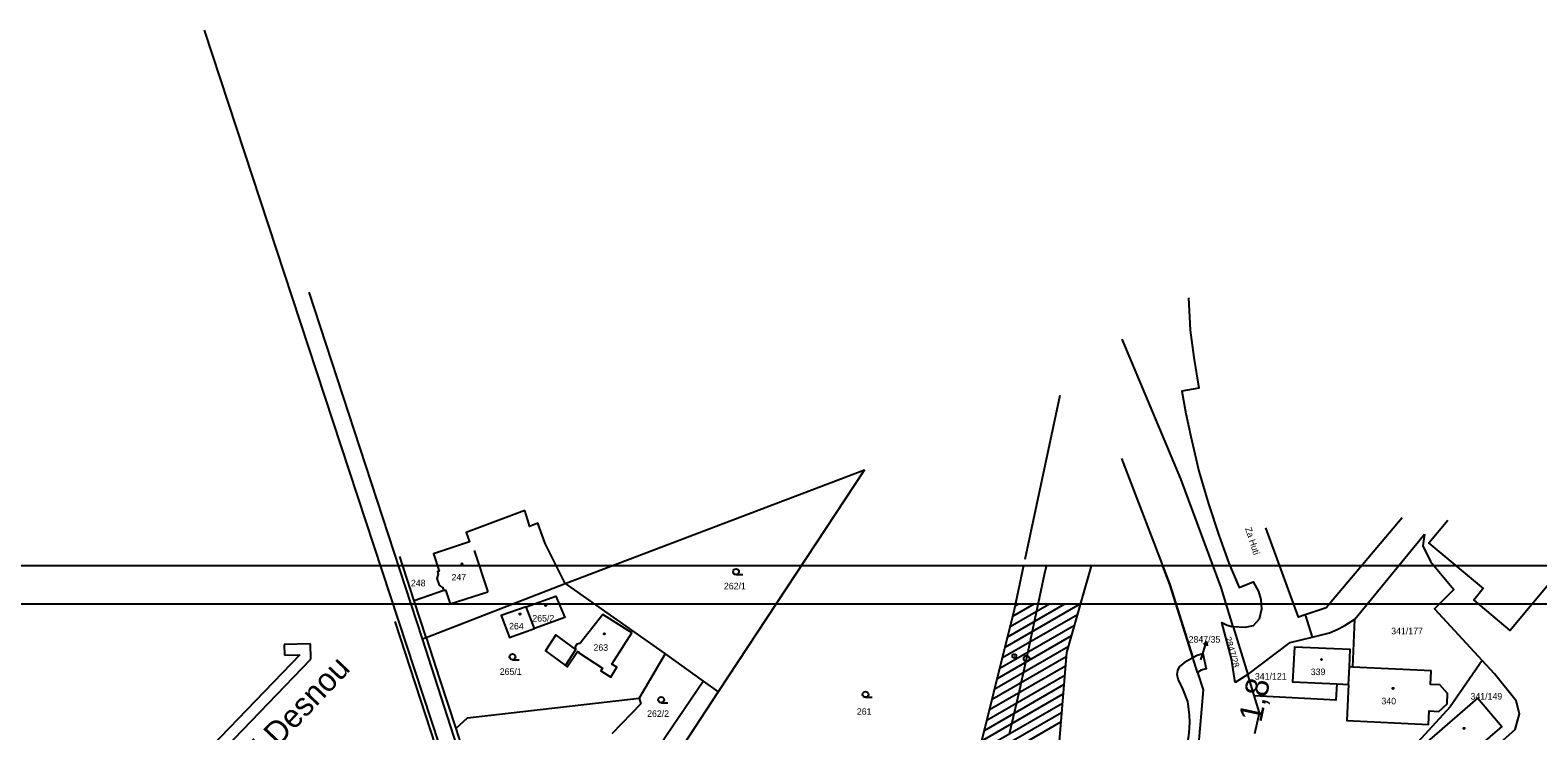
# Model space of a CAD drawing. Extents: x -558500 to -557517, y -1073973 to -1073051.
# Drawn here: x -558300.8 to -557909.9, y -1073232.9 to -1073051.2 of the extents above; entities that cross this region are included whole.
import ezdxf

# ---------------------------------------------------------------- set-up
doc = ezdxf.new("R2010")
doc.units = 0
for name, color, linetype in [('Default', 7, 'Continuous'), ('Hranice parcel', 7, 'Continuous'), ('Kolej', 7, 'Continuous'), ('Návěst místo trati', 7, 'Continuous'), ('Parcelní čísla', 7, 'Continuous'), ('Pop  PČ popisy', 7, 'Continuous'), ('Svazek obcí údolí Desné', 7, 'Continuous'), ('Vnitřní kresba', 7, 'Continuous'), ('Vrstva 1', 7, 'Continuous'), ('Značky budov', 7, 'Continuous'), ('Značky kultur', 7, 'Continuous')]:
    doc.layers.add(name, color=color, linetype=linetype)

msp = doc.modelspace()

# ---------------------------------------------------------------- linework, layer by layer
at = {"layer": 'Default'}
msp.add_lwpolyline([(-557909.21, -1073700), (-558500, -1073700), (-558500, -1073200), (-557800, -1073200), (-557800, -1073567.6)], dxfattribs=at)
at = {"layer": 'Hranice parcel'}
for p, q in [((-558199.08, -1073209.06), (-558228.45, -1073119.15)), ((-558162.11, -1073194.7), (-558084.5, -1073165.24)), ((-558084.5, -1073165.24), (-558122.4, -1073222.85)), ((-557957.38, -1073203.94), (-557939.31, -1073181.91)), ((-558201.24, -1073199.21), (-558204.98, -1073187.73)), ((-558198.15, -1073208.7), (-558162.11, -1073194.7)), ((-558162.11, -1073194.7), (-558136.18, -1073212.99)), ((-558198.15, -1073208.7), (-558201.24, -1073199.21)), ((-558170.04, -1073206.37), (-558172.21, -1073200.74)), ((-558195.64, -1073236.88), (-558206.21, -1073204.6)), ((-557990.44, -1073205.56), (-557988.88, -1073205.99)), ((-557988.88, -1073205.99), (-557985.13, -1073218.31)), ((-557985.87, -1073206.17), (-557988.88, -1073205.99)), ((-557970.23, -1073202.86), (-557968.43, -1073208.63)), ((-557957.84, -1073216.4), (-557957.38, -1073203.94)), ((-558199.08, -1073209.06), (-558198.15, -1073208.7)), ((-558171.71, -1073294.39), (-558199.08, -1073209.06)), ((-557974.16, -1073210.07), (-557968.43, -1073208.63)), ((-558136.18, -1073212.99), (-558142.95, -1073224.45)), ((-558136.18, -1073212.99), (-558126.3, -1073220.06)), ((-557999.34, -1073213.91), (-557998.27, -1073213.29)), ((-557985.13, -1073218.31), (-557974.16, -1073210.07)), ((-558000.9, -1073214.81), (-557999.34, -1073213.91)), ((-557998.11, -1073217.81), (-557999.34, -1073213.91)), ((-557997.23, -1073217.21), (-557998.11, -1073217.81)), ((-557958.95, -1073220.92), (-557958.74, -1073216.36)), ((-557957.84, -1073216.4), (-557958.74, -1073216.36)), ((-557924.3, -1073214.73), (-557932.67, -1073226.72)), ((-558140.75, -1073241.36), (-558126.3, -1073220.06)), ((-558126.3, -1073220.06), (-558122.4, -1073222.85)), ((-557985.13, -1073218.31), (-557988.34, -1073220.45)), ((-557983.46, -1073223.81), (-557985.13, -1073218.31)), ((-557961.95, -1073220.78), (-557958.95, -1073220.92)), ((-558122.4, -1073222.85), (-558147.61, -1073261.18)), ((-557932.67, -1073226.72), (-557943.85, -1073239.02)), ((-558190.48, -1073232.36), (-558186.42, -1073245.02))]:
    msp.add_line(p, q, dxfattribs=at)
for points in [[(-558194.69, -1073236.56), (-558230.74, -1073126.95), (-558255.65, -1073051.21)], [(-558000.52, -1073120.65), (-558000.04, -1073129.01), (-557999.11, -1073136.15), (-557997.8, -1073144.09), (-558002.18, -1073144.84), (-558001.16, -1073150.6), (-557999.9, -1073156.63), (-557997.77, -1073165.6), (-557995.29, -1073174.11), (-557992.59, -1073182.21), (-557990.03, -1073189.46), (-557987.35, -1073195.77), (-557983.68, -1073194.26), (-557982.33, -1073196.81), (-557981.76, -1073198.85), (-557981.57, -1073201.43), (-557982.14, -1073203.98), (-557983.75, -1073205.73), (-557985.87, -1073206.17)], [(-557988.88, -1073205.99), (-557991.98, -1073195.8), (-558002.46, -1073167.55), (-558017.66, -1073131.36)], [(-558017.89, -1073162.31), (-558005.3, -1073194.99), (-557999.34, -1073213.91)], [(-558172.6, -1073175.79), (-558187.75, -1073181.54), (-558186.95, -1073183.95), (-558196.26, -1073187), (-558194.79, -1073191.52), (-558195.22, -1073191.66), (-558195, -1073192.32), (-558195.36, -1073193.46), (-558194.8, -1073195.19), (-558193.84, -1073195.82), (-558193.6, -1073196.55), (-558201.24, -1073199.21)], [(-558162.11, -1073194.7), (-558167.28, -1073184.33), (-558169.22, -1073179.04), (-558171.35, -1073179.92), (-558171.57, -1073179.2), (-558172.6, -1073175.79)], [(-557945.06, -1073177.72), (-557964.79, -1073201.02), (-557968.13, -1073202.16), (-557970.23, -1073202.86)], [(-557933.22, -1073178.38), (-557938.16, -1073184.28), (-557924.03, -1073196.06), (-557926.52, -1073199.04), (-557917.14, -1073206.89), (-557900.5, -1073186.91)], [(-557970.23, -1073202.86), (-557971.99, -1073203.45), (-557980.44, -1073180.31)], [(-557939.31, -1073181.91), (-557939.68, -1073184.93), (-557937.77, -1073189.03), (-557931.69, -1073196.32), (-557936.68, -1073201.34), (-557924.3, -1073214.73)], [(-558172.21, -1073200.74), (-558164.51, -1073198.05), (-558162.21, -1073203.59), (-558170.04, -1073206.37)], [(-558172.21, -1073200.74), (-558178.74, -1073203.06), (-558176.58, -1073208.71), (-558170.04, -1073206.37)], [(-558159.35, -1073211.86), (-558164.49, -1073208.05), (-558167.25, -1073212.17), (-558162.05, -1073216.04), (-558161.61, -1073216.37), (-558158.87, -1073212.35), (-558158.54, -1073212.45), (-558158.65, -1073212.62), (-558152.39, -1073216.66), (-558152.86, -1073217.38), (-558150.28, -1073218.99), (-558148.7, -1073216.44), (-558149.97, -1073215.63), (-558144.81, -1073207.5), (-558152.32, -1073202.74), (-558158.11, -1073210.08), (-558158.35, -1073210.31), (-558159.12, -1073210.49), (-558159.48, -1073211.13), (-558159.35, -1073211.86)], [(-557988.34, -1073220.45), (-557989.32, -1073214.27), (-557991.8, -1073204.87), (-557990.44, -1073205.56)], [(-557968.43, -1073208.63), (-557963.9, -1073207.49), (-557961.96, -1073206.66), (-557959.95, -1073205.6), (-557957.38, -1073203.94)], [(-558198.15, -1073208.7), (-558194.7, -1073219.45), (-558190.48, -1073232.36)], [(-557998.27, -1073213.29), (-557996.72, -1073212.87), (-557995.91, -1073216.87), (-557997.23, -1073217.21)], [(-557958.74, -1073216.36), (-557958.53, -1073211.88), (-557973.01, -1073211.21), (-557973.48, -1073220.25), (-557961.95, -1073220.78)], [(-557998.11, -1073217.81), (-557996.7, -1073222.28), (-557998.38, -1073242.39), (-558002.78, -1073257.43), (-558008.62, -1073269.37), (-558024.06, -1073293.44), (-558032.02, -1073303.96), (-558033.31, -1073305.78)], [(-557958.95, -1073220.92), (-557959.44, -1073230.26), (-557938.22, -1073231.3), (-557938.05, -1073227.77), (-557935.56, -1073227.89), (-557933.42, -1073225.91), (-557933.29, -1073223.26), (-557935.3, -1073221.04), (-557937.72, -1073220.92), (-557937.55, -1073217.37), (-557957.84, -1073216.4)], [(-557920.64, -1073242.45), (-557923.35, -1073239.36), (-557915.81, -1073232.62), (-557914.61, -1073228.54), (-557915.51, -1073225.19), (-557921.13, -1073218.15), (-557924.3, -1073214.73)], [(-557983.46, -1073223.81), (-557962.16, -1073224.87), (-557961.95, -1073220.78)], [(-558190.48, -1073232.36), (-558187.44, -1073229.54), (-558142.95, -1073224.45)], [(-558142.95, -1073224.45), (-558142.49, -1073225.95), (-558150.02, -1073233.76)], [(-557983.29, -1073233.62), (-557982.1, -1073228.28), (-557983.46, -1073223.81)], [(-557937.69, -1073241), (-557937.08, -1073240.47), (-557937.28, -1073240.24), (-557937.09, -1073240.08), (-557939.85, -1073236.97), (-557925.45, -1073224.49), (-557919.26, -1073231.82), (-557925.44, -1073237.21), (-557925.27, -1073237.41), (-557926.88, -1073238.81), (-557927.05, -1073238.61), (-557930.56, -1073241.68)]]:
    msp.add_lwpolyline(points, dxfattribs=at)
at = {"layer": 'Kolej'}
msp.add_lwpolyline([(-558046.86, -1073233.73), (-558044.36, -1073223.02), (-558042.07, -1073212.37), (-558037.79, -1073192.43), (-558037.25, -1073189.91)], dxfattribs=at)
at = {"layer": 'Návěst místo trati'}
msp.add_line((-558045.69, -1073213.53), (-558045.59, -1073213.53), dxfattribs=at)
for centre, radius in [((-558045.64, -1073213.53), 0.5), ((-558042.46, -1073214.22), 0.75)]:
    msp.add_circle(centre, radius, dxfattribs=at)
at = {"layer": 'Pop  PČ popisy'}
for p, q in [((-557996.68, -1073212.64), (-557995.8, -1073209.77)), ((-557995.8, -1073209.77), (-557996.57, -1073210.58)), ((-557995.8, -1073209.77), (-557995.62, -1073210.87)), ((-557997.26, -1073214.56), (-557996.68, -1073212.64))]:
    msp.add_line(p, q, dxfattribs=at)
at = {"layer": 'Svazek obcí údolí Desné'}
for p, q in [((-558048.03, -1073211.26), (-558028.53, -1073200)), ((-558047.36, -1073208.56), (-558032.53, -1073200)), ((-558046.69, -1073205.87), (-558036.53, -1073200)), ((-558046.02, -1073203.17), (-558040.53, -1073200)), ((-558045.39, -1073200.5), (-558044.53, -1073200)), ((-558049.37, -1073216.65), (-558030.08, -1073205.52)), ((-558048.7, -1073213.96), (-558029.3, -1073202.76)), ((-558050.04, -1073219.35), (-558030.86, -1073208.28)), ((-558051.39, -1073224.74), (-558032.18, -1073213.65)), ((-558050.71, -1073222.05), (-558031.64, -1073211.03)), ((-558052.06, -1073227.44), (-558032.38, -1073216.08)), ((-558053.4, -1073232.84), (-558032.78, -1073220.93)), ((-558052.73, -1073230.14), (-558032.58, -1073218.51)), ((-558054.07, -1073235.53), (-558032.98, -1073223.36)), ((-558055.41, -1073240.93), (-558033.39, -1073228.21)), ((-558054.74, -1073238.23), (-558033.19, -1073225.78)), ((-558056.08, -1073243.62), (-558033.59, -1073230.64))]:
    msp.add_line(p, q, dxfattribs=at)
for points in [[(-558042.8, -1073188.38), (-558033.73, -1073145.86)], [(-558082.18, -1073306.93), (-558073.77, -1073292.96), (-558066.53, -1073276.76), (-558060.05, -1073257.85), (-558056.4, -1073244.89), (-558045.6, -1073201.5), (-558043.14, -1073189.96)], [(-558025.67, -1073189.86), (-558032.09, -1073212.63), (-558035.15, -1073249.33), (-558039.97, -1073265.01), (-558041.24, -1073272.26), (-558045.55, -1073290.79), (-558055.77, -1073312.33), (-558066.64, -1073329.29), (-558067.37, -1073328.67), (-558071.91, -1073335.47), (-558071.45, -1073339.78), (-558072.38, -1073341.74), (-558078.52, -1073350.81)], [(-558066.74, -1073350.64), (-558065.9, -1073348.86), (-558061.08, -1073328.44), (-558060.65, -1073327.54), (-558046.7, -1073313.29), (-558030.4, -1073296.27), (-558015.33, -1073274.48), (-558010.02, -1073266.4), (-558006.82, -1073259.79), (-558003.58, -1073251.39), (-558001.93, -1073245.63), (-558000.3, -1073233.47), (-558000.14, -1073230.76), (-558000.21, -1073228.76), (-558000.67, -1073225.31), (-558001.93, -1073222.03), (-558003.18, -1073219.55), (-558003.41, -1073218.32), (-558003.28, -1073217.31), (-558002.8, -1073216.38), (-558000.9, -1073214.81), (-557999.34, -1073213.91), (-558005.3, -1073194.99), (-558007.3, -1073189.81)]]:
    msp.add_lwpolyline(points, dxfattribs=at)
at = {"layer": 'Vnitřní kresba'}
for p, q in [((-558185.69, -1073186.21), (-558182.14, -1073196.86)), ((-558193.6, -1073196.55), (-558193.1, -1073196.39)), ((-558193.1, -1073196.39), (-558191.93, -1073199.98)), ((-558191.93, -1073199.98), (-558182.14, -1073196.86)), ((-558162.05, -1073216.04), (-558159.35, -1073211.86))]:
    msp.add_line(p, q, dxfattribs=at)
at = {"layer": 'Vrstva 1'}
for p, q in [((-558357.53, -1073190.09), (-557516.53, -1073190.09)), ((-558230.95, -1073213.27), (-558278.82, -1073262.89)), ((-558228.16, -1073210.39), (-558235.01, -1073210.51)), ((-558235.01, -1073210.51), (-558234.9, -1073213.34)), ((-558234.9, -1073213.34), (-558230.95, -1073213.27)), ((-558228.09, -1073214.39), (-558228.16, -1073210.39)), ((-558276.78, -1073264.86), (-558228.09, -1073214.39))]:
    msp.add_line(p, q, dxfattribs=at)
at = {"layer": 'Značky budov'}
for centre in [(-558188.83, -1073189.63), (-558167.13, -1073200.43), (-558173.84, -1073202.67), (-558151.98, -1073207.78), (-557965.99, -1073214.44), (-557947.45, -1073221.95), (-557929.04, -1073232.33)]:
    msp.add_circle(centre, 0.175, dxfattribs=at)
at = {"layer": 'Značky kultur'}
for p, q in [((-558117.8, -1073192.42), (-558116.05, -1073192.42)), ((-558175.76, -1073214.51), (-558174.01, -1073214.51)), ((-558084.24, -1073224.25), (-558082.49, -1073224.25)), ((-558137.22, -1073225.64), (-558135.47, -1073225.64))]:
    msp.add_line(p, q, dxfattribs=at)
for centre in [(-558117.8, -1073191.67), (-558175.76, -1073213.76), (-558137.22, -1073224.89), (-558084.24, -1073223.5)]:
    msp.add_circle(centre, 0.75, dxfattribs=at)

# ---------------------------------------------------------------- texts
at = {"layer": 'Návěst místo trati'}
msp.add_text('1,8', height=6, rotation=77.8693, dxfattribs=at).set_placement((-557981.63, -1073230.98))
at = {"layer": 'Parcelní čísla'}
for s, p in [('248', (-558202.11, -1073195.47)), ('247', (-558191.57, -1073193.95)), ('262/1', (-558120.95, -1073196.24)), ('264', (-558176.65, -1073206.64)), ('265/2', (-558170.62, -1073204.6)), ('2847/35', (-558000.44, -1073210.07)), ('341/177', (-557947.92, -1073207.91)), ('263', (-558154.76, -1073212.19)), ('265/1', (-558179.07, -1073218.43)), ('339', (-557968.77, -1073218.49)), ('341/121', (-557983.26, -1073219.67)), ('340', (-557950.45, -1073226.08)), ('341/149', (-557927.35, -1073224.83)), ('262/2', (-558140.86, -1073229.32)), ('261', (-558086.47, -1073228.79))]:
    msp.add_text(s, height=1.7, dxfattribs=at).set_placement(p)
msp.add_text('2847/28', height=1.7, rotation=286, dxfattribs=at).set_placement((-557991.1, -1073208.79))
at = {"layer": 'Pop  PČ popisy'}
msp.add_text('Za Hutí', height=1.7, rotation=288, dxfattribs=at).set_placement((-557985.84, -1073180.45))
at = {"layer": 'Vrstva 1'}
msp.add_text('Kouty nad Desnou', height=6, rotation=46.6457, dxfattribs=at).set_placement((-558262.82, -1073265.06))

doc.saveas('drawing.dxf')
